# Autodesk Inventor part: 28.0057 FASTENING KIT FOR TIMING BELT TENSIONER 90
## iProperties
Created: 2007-06
Part Number: 28.0057 FASTENING KIT FOR TIMING BELT TENSIONER 90
Document SubType Name: Modeling
Designer: Andy Moles
Material: Aluminum-6061
Description: 1/2" OR 12mm THICK AL PLATE MAKE TO DETAL 1
Density: 2.71 g/cm^3
Author: Andy Moles
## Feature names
1. Extrusion1
2. Hole1
